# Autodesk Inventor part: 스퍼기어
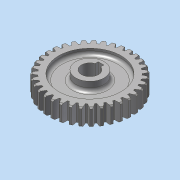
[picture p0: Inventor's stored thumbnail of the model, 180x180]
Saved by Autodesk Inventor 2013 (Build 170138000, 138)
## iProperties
Created: 2013-08
Part Number: 스퍼기어
Material: 강
Document SubType Name: Modeling
Designer: 한국산업디자인학원
Categories: <?xml version="1.0" encoding="UTF-16"?> <MemberInstance><Categories><FamilyTemplate><FamilyTemplateParameter ValueType="xs:double" Id="1" ObjectReferenceKey="da
Density: 1 g/cm^3
CustomPartVersion: 1
Author: 한국산업디자인학원
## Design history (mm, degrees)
sketch "Sketch1"
  geometry: C1 r 37 at (0, 0)
  constraints: 1 centre point
  dimensions: "d0" = 74 diameter of C1 (= da_da)
extrude "Extrusion1" new body sketch "Sketch1" distance "d1" = 15 (= da_b); taper "d2" = 0 deg
workplane "Work Plane2"
feature "피치 지름" dims "d4" = 10, "d5" = 0
workplane "Work Plane8"
workplane "Work Plane9"
chamfer "모따기1" distance "d49" = 1; stored, may be unused: second distance "d50" = 2, angle "d51" = 45 deg
feature "스퍼 기어" dims "da_b" = 15, "da_d" = 70, "da_aw" = 70, "da_da" = 74, "da_df" = 65, "da_dw" = 70, angle "da_beta" = 0 deg, "da_lefttooth" = 0, "da_righttooth" = 0
node "작업 평면11"
sketch "스케치3"
  geometry: C1 r 12.5 at (0, 0); 1 further point
  constraints: 1 centre point, 1 coincident
  dimensions: "d53" = 25 diameter of C1
extrude "돌출2" join sketch "스케치3" distance "d55" = 31; taper "d56" = 0 deg
sketch "스케치4"
  geometry: L1 (-2.5, 7.071)-(-2.5, 9.8); L2 (-2.5, 9.8)-(2.5, 9.8); L3 (2.5, 9.8)-(2.5, 7.071); C1 r 12.5 at (0, 0) reference; A1 r 7.5 centre (0, 0) between (-2.5, 7.071) and (2.5, 7.071)
  constraints: 6 end point, 2 parallel, 2 point on circle, 1 centre point, 1 coincident, 1 perpendicular, 1 vertical
  dimensions: "d57" = 15 diameter of A1; "d59" = 5 distance of L1.end L2.end; "d60" = 17.3 dimension on A1 L2
extrude "돌출3" cut sketch "스케치4" stored distance "d61" = 31; taper "d62" = 0 deg
sketch "스케치5"
  geometry: C1 r 12.5 at (0, 0) reference; C2 r 27.5 at (0, 0); A1 r 32.5 centre (0, 0) between (9.347, 31.127) and (7.941, 31.515) reference
  constraints: 1 centre point, 1 coincident
  dimensions: "d63" = 55 diameter of C2
extrude "돌출4" cut sketch "스케치5" distance "d65" = 5; taper "d66" = 0 deg
sketch "스케치6"
  geometry: C1 r 12.5 at (0, 0) reference; C2 r 27.5 at (0, 0); A1 r 36 centre (0, 0) between (-5.215, 35.62) and (-7.633, 35.181) reference
  constraints: 1 centre point, 1 coincident
  dimensions: "d67" = 55 diameter of C2
extrude "돌출5" cut sketch "스케치6" distance "d69" = 5; taper "d70" = 0 deg
fillet "모깎기1" dims "d71" = 3
body "Solid1"
sketch "Sketch2"
  geometry: C1 r 37 at (0, 0) reference; C2 r 35 at (0, 0)
  constraints: 1 centre point, 1 coincident
  dimensions: "d3" = 70 diameter of C2 (= da_dw)
body "Srf1"
other parameters: "d17" = 0, "d34" = 0.8976 (computed from da_z), "d39" = 0, "d41" = 0, "d47" = 0, "d48" = 0, "d52" = 3
